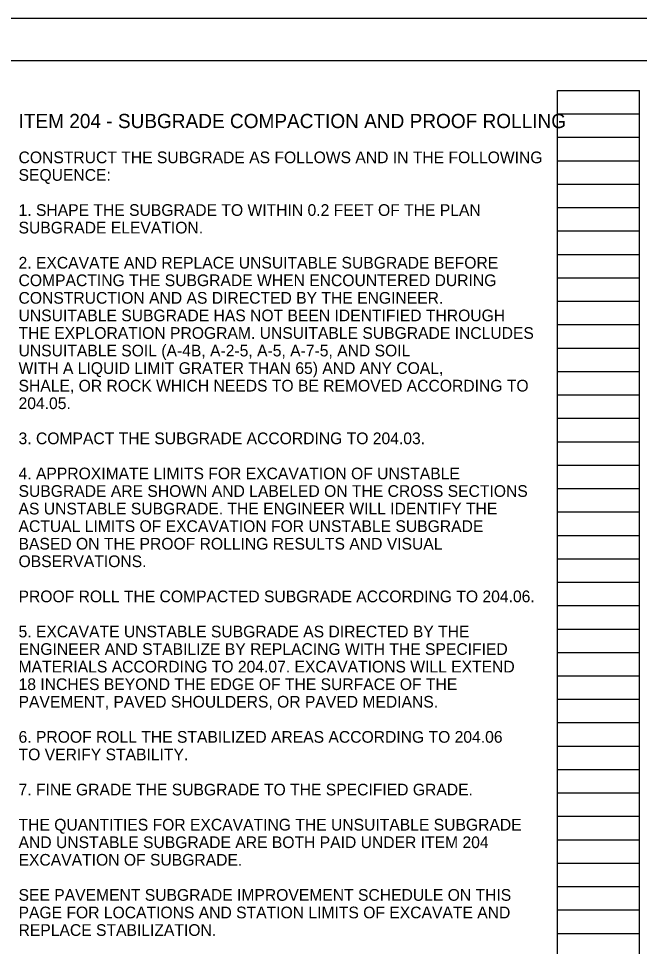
# Model space of a CAD drawing. Extents: x 0 to 34, y 0 to 22.
# Drawn here: x 10.32 to 17.74, y 10.9 to 22 of the extents above; entities that cross this region are included whole.
import ezdxf

# ---------------------------------------------------------------- set-up
doc = ezdxf.new("R2010")
doc.units = 0
for name, color, linetype in [('SC_Scratch1', 7, 'Continuous'), ('SH_Border', 7, 'Continuous'), ('SH_Cut_Line', 7, 'Continuous'), ('TX_P_1', 7, 'Continuous')]:
    doc.layers.add(name, color=color, linetype=linetype)

msp = doc.modelspace()

# ---------------------------------------------------------------- linework, layer by layer
at = {"layer": 'SC_Scratch1'}
for p, q in [((16.76, 0.98), (16.76, 21.14)), ((16.76, 21.14), (17.74, 21.14)), ((17.74, 0.98), (17.74, 21.14)), ((16.76, 20.86), (17.74, 20.86)), ((16.76, 20.58), (17.74, 20.58)), ((16.76, 20.3), (17.74, 20.3)), ((16.76, 20.02), (17.74, 20.02)), ((16.76, 19.74), (17.74, 19.74)), ((16.76, 19.46), (17.74, 19.46)), ((16.76, 19.18), (17.74, 19.18)), ((16.76, 18.9), (17.74, 18.9)), ((16.76, 18.62), (17.74, 18.62)), ((16.76, 18.34), (17.74, 18.34)), ((16.76, 18.06), (17.74, 18.06)), ((16.76, 17.78), (17.74, 17.78)), ((16.76, 17.5), (17.74, 17.5)), ((16.76, 17.22), (17.74, 17.22)), ((16.76, 16.94), (17.74, 16.94)), ((16.76, 16.66), (17.74, 16.66)), ((16.76, 16.38), (17.74, 16.38)), ((16.76, 16.1), (17.74, 16.1)), ((16.76, 15.82), (17.74, 15.82)), ((16.76, 15.54), (17.74, 15.54)), ((16.76, 15.26), (17.74, 15.26)), ((16.76, 14.98), (17.74, 14.98)), ((16.76, 14.7), (17.74, 14.7)), ((16.76, 14.42), (17.74, 14.42)), ((16.76, 14.14), (17.74, 14.14)), ((16.76, 13.86), (17.74, 13.86)), ((16.76, 13.58), (17.74, 13.58)), ((16.76, 13.3), (17.74, 13.3)), ((16.76, 13.02), (17.74, 13.02)), ((16.76, 12.74), (17.74, 12.74)), ((16.76, 12.46), (17.74, 12.46)), ((16.76, 12.18), (17.74, 12.18)), ((16.76, 11.9), (17.74, 11.9)), ((16.76, 11.62), (17.74, 11.62)), ((16.76, 11.34), (17.74, 11.34)), ((16.76, 11.06), (17.74, 11.06))]:
    msp.add_line(p, q, dxfattribs=at)
at = {"layer": 'SH_Border'}
msp.add_lwpolyline([(2, 21.5), (33.5, 21.5), (33.5, 0.5), (2, 0.5)], close=True, dxfattribs=at)
at = {"layer": 'SH_Cut_Line'}
msp.add_lwpolyline([(0, 0), (34, 0), (34, 22), (0, 22)], close=True, dxfattribs=at)

# ---------------------------------------------------------------- texts
at = {"layer": 'TX_P_1'}
for s, height, p in [('ITEM 204 - SUBGRADE COMPACTION AND PROOF ROLLING', 0.17, (10.32, 20.69)), ('CONSTRUCT THE SUBGRADE AS FOLLOWS AND IN THE FOLLOWING ', 0.14, (10.32, 20.27)), ('SEQUENCE: ', 0.14, (10.32, 20.06)), ('1. SHAPE THE SUBGRADE TO WITHIN 0.2 FEET OF THE PLAN ', 0.14, (10.32, 19.64)), ('SUBGRADE ELEVATION.', 0.14, (10.32, 19.43)), ('2. EXCAVATE AND REPLACE UNSUITABLE SUBGRADE BEFORE ', 0.14, (10.32, 19.01)), ('COMPACTING THE SUBGRADE WHEN ENCOUNTERED DURING ', 0.14, (10.32, 18.8)), ('CONSTRUCTION AND AS DIRECTED BY THE ENGINEER. ', 0.14, (10.32, 18.59)), ('UNSUITABLE SUBGRADE HAS NOT BEEN IDENTIFIED THROUGH ', 0.14, (10.32, 18.38)), ('THE EXPLORATION PROGRAM. UNSUITABLE SUBGRADE INCLUDES ', 0.14, (10.32, 18.17)), ('UNSUITABLE SOIL (A-4B, A-2-5, A-5, A-7-5, AND SOIL ', 0.14, (10.32, 17.96)), ('WITH A LIQUID LIMIT GRATER THAN 65) AND ANY COAL, ', 0.14, (10.32, 17.75)), ('SHALE, OR ROCK WHICH NEEDS TO BE REMOVED ACCORDING TO ', 0.14, (10.32, 17.54)), ('204.05.', 0.14, (10.32, 17.33)), ('3. COMPACT THE SUBGRADE ACCORDING TO 204.03.', 0.14, (10.32, 16.91)), ('4. APPROXIMATE LIMITS FOR EXCAVATION OF UNSTABLE ', 0.14, (10.32, 16.49)), ('SUBGRADE ARE SHOWN AND LABELED ON THE CROSS SECTIONS ', 0.14, (10.32, 16.28)), ('AS UNSTABLE SUBGRADE. THE ENGINEER WILL IDENTIFY THE ', 0.14, (10.32, 16.07)), ('ACTUAL LIMITS OF EXCAVATION FOR UNSTABLE SUBGRADE ', 0.14, (10.32, 15.86)), ('BASED ON THE PROOF ROLLING RESULTS AND VISUAL ', 0.14, (10.32, 15.65)), ('OBSERVATIONS.', 0.14, (10.32, 15.44)), ('PROOF ROLL THE COMPACTED SUBGRADE ACCORDING TO 204.06.', 0.14, (10.32, 15.02)), ('5. EXCAVATE UNSTABLE SUBGRADE AS DIRECTED BY THE ', 0.14, (10.32, 14.6)), ('ENGINEER AND STABILIZE BY REPLACING WITH THE SPECIFIED ', 0.14, (10.32, 14.39)), ('MATERIALS ACCORDING TO 204.07. EXCAVATIONS WILL EXTEND ', 0.14, (10.32, 14.18)), ('18 INCHES BEYOND THE EDGE OF THE SURFACE OF THE ', 0.14, (10.32, 13.97)), ('PAVEMENT, PAVED SHOULDERS, OR PAVED MEDIANS.', 0.14, (10.32, 13.76)), ('6. PROOF ROLL THE STABILIZED AREAS ACCORDING TO 204.06 ', 0.14, (10.32, 13.34)), ('TO VERIFY STABILITY.', 0.14, (10.32, 13.13)), ('7. FINE GRADE THE SUBGRADE TO THE SPECIFIED GRADE.', 0.14, (10.32, 12.71)), ('THE QUANTITIES FOR EXCAVATING THE UNSUITABLE SUBGRADE ', 0.14, (10.32, 12.29)), ('AND UNSTABLE SUBGRADE ARE BOTH PAID UNDER ITEM 204 ', 0.14, (10.32, 12.08)), ('EXCAVATION OF SUBGRADE.', 0.14, (10.32, 11.87)), ('SEE PAVEMENT SUBGRADE IMPROVEMENT SCHEDULE ON THIS ', 0.14, (10.32, 11.45)), ('PAGE FOR LOCATIONS AND STATION LIMITS OF EXCAVATE AND ', 0.14, (10.32, 11.24)), ('REPLACE STABILIZATION.', 0.14, (10.32, 11.03))]:
    msp.add_text(s, height=height, dxfattribs=at).set_placement(p)

doc.saveas('drawing.dxf')
